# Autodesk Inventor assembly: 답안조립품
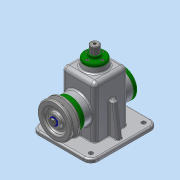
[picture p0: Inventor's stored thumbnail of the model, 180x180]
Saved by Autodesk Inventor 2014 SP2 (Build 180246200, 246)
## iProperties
Created: 2016-08
Part Number: 답안조립품
Document SubType Name: Assembly
Designer: user
Author: user
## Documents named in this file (19)
- C:\Users\user\Desktop\460820V1023\답안조립품.iam
- C:\Users\user\Desktop\460820V1023\본체.ipt
- C:\Users\user\Desktop\460820V1023\베어링 15 x 35 x 11.ipt
- C:\Users\user\Desktop\460820V1023\상부부시.ipt
- C:\Users\user\Desktop\460820V1023\편심축.ipt
- C:\Users\user\Desktop\460820V1023\링크.ipt
- C:\Users\user\Desktop\460820V1023\고정핀.ipt
- C:\Users\user\Desktop\460820V1023\멈춤링 6 x 5.ipt
- C:\Users\user\Desktop\460820V1023\슬라이드바.ipt
- C:\Users\user\Desktop\460820V1023\멈춤링 15 x 1.ipt
- C:\Users\user\Desktop\460820V1023\와셔.ipt
- C:\Users\user\Desktop\460820V1023\뒤커버.ipt
- C:\Users\user\Desktop\460820V1023\앞커버.ipt
- C:\Users\user\Desktop\460820V1023\오일실 15 25 7.ipt
- C:\Users\user\Desktop\460820V1023\볼트 M3 x 8.ipt
- C:\Users\user\Desktop\460820V1023\볼트 M4 x 10.ipt
- C:\Users\user\Desktop\460820V1023\V-벨트풀리.ipt
- C:\Users\user\Desktop\460820V1023\키 5 x 5 x 14.ipt
- C:\Users\user\Desktop\460820V1023\볼트 M6 x 12.ipt
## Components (15 placed, 5 different names)
1. 고정핀:1 — 강체:1, 강체:2
2. V-벨트풀리:1 — 각도:1, 구동
3. ISO 4018 M6 x 12:1 — 강체:9
4. ISO 4762 M3 x 8:1 — 강체:5
5. ISO 4762 M3 x 8:2
6. ISO 4762 M3 x 8:3
7. ISO 4762 M3 x 8:4
8. ISO 4762 M4 x 10:2 — 강체:7
9. ISO 4762 M4 x 10:1 — 강체:6
10. ISO 4762 M4 x 10:3
11. ISO 4762 M4 x 10:4
12. ISO 4762 M4 x 10:5
13. ISO 4762 M4 x 10:6
14. ISO 4762 M4 x 10:7
15. ISO 4762 M4 x 10:8
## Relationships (8: WeldJoint 6, Angle 2)
- 강체:1 [WeldJoint]: 고정핀:1
- 강체:2 [WeldJoint]: 고정핀:1
- 강체:5 [WeldJoint]: ISO 4762 M3 x 8:1
- 강체:6 [WeldJoint]: ISO 4762 M4 x 10:1
- 강체:7 [WeldJoint]: ISO 4762 M4 x 10:2
- 각도:1 [Angle]: V-벨트풀리:1
- 강체:9 [WeldJoint]: ISO 4018 M6 x 12:1
- 구동 [Angle]: V-벨트풀리:1
